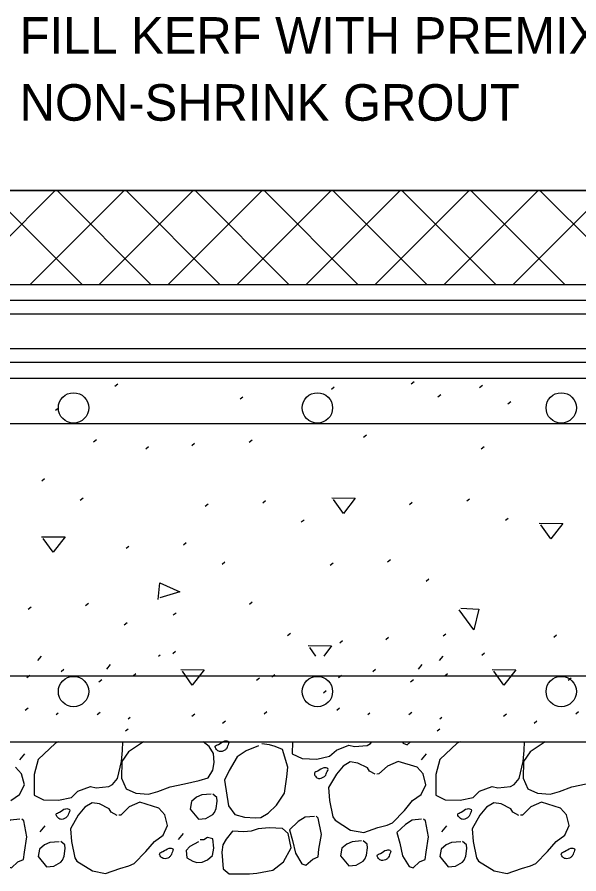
# Model space of a CAD drawing. Extents: x 3239 to 4230, y -4276 to -2494.
# Drawn here: x 3413 to 3459.1, y -4182.4 to -4112.1 of the extents above; entities that cross this region are included whole.
import ezdxf

# ---------------------------------------------------------------- set-up
doc = ezdxf.new("R2010")
doc.units = 0
doc.layers.add('2', color=7, linetype='Continuous')

msp = doc.modelspace()

# ---------------------------------------------------------------- linework, layer by layer
at = {"layer": '2'}
for p, q in [((3367.086, -4126.29), (3545.886, -4126.29)), ((3408.444, -4133.99), (3416.144, -4126.29)), ((3410.64, -4126.29), (3418.34, -4133.99)), ((3414.1, -4133.99), (3421.8, -4126.29)), ((3416.297, -4126.29), (3423.997, -4133.99)), ((3419.757, -4133.99), (3427.457, -4126.29)), ((3421.953, -4126.29), (3429.653, -4133.99)), ((3425.414, -4133.99), (3433.114, -4126.29)), ((3427.61, -4126.29), (3435.31, -4133.99)), ((3431.071, -4133.99), (3438.771, -4126.29)), ((3433.267, -4126.29), (3440.967, -4133.99)), ((3436.728, -4133.99), (3444.428, -4126.29)), ((3438.924, -4126.29), (3446.624, -4133.99)), ((3442.385, -4133.99), (3450.085, -4126.29)), ((3444.581, -4126.29), (3452.281, -4133.99)), ((3448.042, -4133.99), (3455.742, -4126.29)), ((3450.238, -4126.29), (3457.938, -4133.99)), ((3453.698, -4133.99), (3461.398, -4126.29)), ((3455.895, -4126.29), (3463.595, -4133.99)), ((3363.086, -4133.99), (3601.998, -4133.99)), ((3373.167, -4135.293), (3504.55, -4135.293)), ((3365.857, -4136.415), (3504.55, -4136.415)), ((3365.857, -4139.265), (3504.55, -4139.265)), ((3365.857, -4139.265), (3504.55, -4139.265)), ((3373.167, -4140.387), (3504.55, -4140.387)), ((3351.09, -4141.69), (3512.455, -4141.69)), ((3421.032, -4142.344), (3421.265, -4142.158)), ((3445.343, -4142.147), (3445.576, -4141.96)), ((3450.944, -4142.454), (3451.177, -4142.267)), ((3438.796, -4142.589), (3439.029, -4142.403)), ((3447.533, -4143.227), (3447.766, -4143.041)), ((3431.306, -4143.392), (3431.539, -4143.206)), ((3453.27, -4143.791), (3453.503, -4143.605)), ((3416.163, -4144.324), (3416.395, -4144.138)), ((3311.806, -4145.411), (3542.451, -4145.411)), ((3441.429, -4146.527), (3441.662, -4146.34)), ((3419.284, -4146.902), (3419.517, -4146.715)), ((3427.346, -4147.213), (3427.579, -4147.027)), ((3432.049, -4146.931), (3432.282, -4146.745)), ((3423.571, -4147.493), (3423.804, -4147.307)), ((3451.084, -4147.486), (3451.317, -4147.3)), ((3415.032, -4150.106), (3415.265, -4149.92)), ((3418.201, -4151.69), (3418.434, -4151.504)), ((3428.454, -4152.188), (3428.687, -4152.002)), ((3433.157, -4151.906), (3433.39, -4151.719)), ((3445.196, -4152.049), (3445.429, -4151.863)), ((3449.899, -4151.767), (3450.132, -4151.581)), ((3436.326, -4153.49), (3436.559, -4153.304)), ((3453.068, -4153.352), (3453.301, -4153.165)), ((3421.951, -4155.649), (3422.184, -4155.463)), ((3426.654, -4155.367), (3426.887, -4155.18)), ((3429.823, -4156.951), (3430.056, -4156.765)), ((3438.693, -4157.033), (3438.926, -4156.847)), ((3443.396, -4156.751), (3443.629, -4156.565)), ((3446.565, -4158.336), (3446.798, -4158.149)), ((3413.926, -4160.633), (3414.159, -4160.447)), ((3418.629, -4160.351), (3418.862, -4160.164)), ((3432.072, -4160.234), (3432.305, -4160.048)), ((3425.829, -4161.12), (3426.062, -4160.933)), ((3421.798, -4161.935), (3422.031, -4161.749)), ((3435.194, -4162.812), (3435.427, -4162.625)), ((3447.959, -4162.841), (3448.192, -4162.655)), ((3457.025, -4162.933), (3457.258, -4162.746)), ((3439.481, -4163.403), (3439.714, -4163.216)), ((3443.255, -4163.123), (3443.488, -4162.937)), ((3425.782, -4164.288), (3426.015, -4164.102)), ((3424.621, -4164.49), (3424.757, -4164.381)), ((3451.128, -4164.425), (3451.361, -4164.239)), ((3416.622, -4165.75), (3416.855, -4165.563)), ((3442.179, -4165.75), (3442.412, -4165.563)), ((3310.367, -4166.121), (3542.451, -4166.121)), ((3413.821, -4166.243), (3414.054, -4166.056)), ((3422.529, -4166.101), (3422.762, -4165.914)), ((3433.921, -4166.196), (3434.154, -4166.01)), ((3439.378, -4166.243), (3439.611, -4166.056)), ((3448.085, -4166.101), (3448.318, -4165.914)), ((3419.728, -4166.594), (3419.961, -4166.407)), ((3432.663, -4166.476), (3432.896, -4166.29)), ((3445.285, -4166.594), (3445.518, -4166.407)), ((3458.22, -4166.476), (3458.453, -4166.29)), ((3438.143, -4167.505), (3438.376, -4167.318)), ((3413.681, -4168.934), (3413.914, -4168.747)), ((3433.273, -4169.226), (3433.506, -4169.04)), ((3439.238, -4168.934), (3439.471, -4168.747)), ((3458.83, -4169.226), (3459.063, -4169.04)), ((3416.219, -4169.28), (3416.391, -4169.142)), ((3419.588, -4169.285), (3419.821, -4169.098)), ((3422.125, -4169.632), (3422.298, -4169.493)), ((3427.358, -4169.415), (3427.591, -4169.229)), ((3441.776, -4169.28), (3441.948, -4169.142)), ((3445.145, -4169.285), (3445.378, -4169.098)), ((3447.682, -4169.632), (3447.855, -4169.493)), ((3452.915, -4169.415), (3453.148, -4169.229)), ((3421.915, -4170.622), (3422.125, -4170.453)), ((3429.862, -4170), (3430.095, -4169.813)), ((3447.471, -4170.622), (3447.682, -4170.453)), ((3455.419, -4170), (3455.652, -4169.813)), ((3310.367, -4171.521), (3545.886, -4171.521))]:
    msp.add_line(p, q, dxfattribs=at)
msp.add_lwpolyline([(3373.586, -4133.99), (3545.886, -4133.99), (3545.886, -4126.29), (3373.586, -4126.29)], close=True, dxfattribs=at)
for points in [[(3438.818, -4151.513), (3440.751, -4151.536), (3439.773, -4152.794), (3438.957, -4151.653)], [(3455.836, -4153.59), (3457.77, -4153.613), (3456.791, -4154.871), (3455.976, -4153.729)], [(3415.019, -4154.697), (3416.953, -4154.721), (3415.975, -4155.979), (3415.159, -4154.837)], [(3424.594, -4159.838), (3424.734, -4158.487), (3426.364, -4159.233), (3424.71, -4159.722)], [(3449.411, -4160.562), (3450.879, -4160.632), (3450.483, -4162.333), (3449.271, -4160.702)], [(3436.878, -4163.636), (3438.812, -4163.659), (3438.165, -4164.49)], [(3437.528, -4164.49), (3437.018, -4163.776)], [(3414.981, -4164.49), (3414.677, -4164.853)], [(3447.924, -4164.49), (3447.62, -4164.853)], [(3420.658, -4165.192), (3420.354, -4165.555)], [(3446.215, -4165.192), (3445.911, -4165.555)], [(3426.432, -4165.594), (3428.366, -4165.618), (3427.388, -4166.876), (3426.572, -4165.734)], [(3451.989, -4165.594), (3453.923, -4165.618), (3452.945, -4166.876), (3452.129, -4165.734)], [(3416.417, -4171.521), (3416.162, -4171.649), (3414.754, -4172.992), (3414.426, -4174.218), (3414.419, -4175.898), (3415.194, -4176.287), (3416.418, -4176.31), (3417.466, -4176.088), (3418.009, -4175.584), (3419.042, -4175.188), (3419.509, -4175.299), (3420.547, -4175.208), (3420.837, -4175.031), (3421.251, -4174.537), (3421.589, -4173.156), (3421.661, -4172.236), (3421.699, -4171.521)], [(3423.391, -4171.521), (3422.149, -4172.345), (3421.611, -4173.154), (3421.576, -4174.509), (3421.958, -4175.39), (3422.753, -4175.756), (3423.804, -4175.817), (3424.548, -4175.599), (3425.562, -4175.228), (3426.759, -4174.97), (3427.936, -4174.715), (3428.679, -4174.496), (3429.08, -4173.852), (3429.18, -4173.233), (3429.115, -4172.498), (3428.759, -4171.918), (3428.284, -4171.521)], [(3432.808, -4171.869), (3431.796, -4172.263), (3431.077, -4172.762), (3430.413, -4173.888), (3430.026, -4174.684), (3430.36, -4176.769), (3430.88, -4177.486), (3431.661, -4177.701), (3432.562, -4177.774), (3433.016, -4177.734), (3433.595, -4177.38), (3434.301, -4176.729), (3434.956, -4175.756), (3435.142, -4174.39), (3435.227, -4173.62), (3434.793, -4172.153), (3434.184, -4171.903), (3433.715, -4171.79), (3433.098, -4171.692)], [(3435.593, -4171.521), (3435.588, -4172.521), (3436.384, -4172.908), (3437.588, -4172.955), (3438.635, -4172.711), (3439.199, -4172.205), (3440.211, -4171.811), (3440.679, -4171.922), (3441.737, -4171.829), (3442.006, -4171.654), (3442.123, -4171.521)], [(3444.607, -4171.521), (3444.685, -4171.647), (3445.001, -4171.771), (3445.27, -4171.521)], [(3449.361, -4171.521), (3449.105, -4171.649), (3447.698, -4172.992), (3447.37, -4174.218), (3447.363, -4175.898), (3448.138, -4176.287), (3449.361, -4176.31), (3450.41, -4176.088), (3450.953, -4175.584), (3451.986, -4175.188), (3452.453, -4175.299), (3453.491, -4175.208), (3453.781, -4175.031), (3454.195, -4174.537), (3454.533, -4173.156), (3454.604, -4172.236), (3454.643, -4171.521)], [(3456.335, -4171.521), (3455.093, -4172.345), (3454.555, -4173.154), (3454.52, -4174.509), (3454.902, -4175.39), (3455.697, -4175.756), (3456.748, -4175.817), (3457.492, -4175.599), (3458.505, -4175.228), (3459.702, -4174.97), (3460.88, -4174.715), (3461.623, -4174.496), (3462.024, -4173.852), (3462.123, -4173.233), (3462.059, -4172.498), (3461.703, -4171.918), (3461.227, -4171.521)], [(3413.635, -4172.507), (3413.219, -4173.003)], [(3446.578, -4172.507), (3446.163, -4173.003)], [(3442.381, -4174.192), (3441.923, -4173.949), (3441.746, -4173.659), (3440.949, -4173.271), (3440.33, -4173.174), (3439.752, -4173.528), (3439.221, -4174.185), (3438.555, -4175.289), (3438.647, -4176.349), (3438.915, -4177.677), (3439.094, -4177.967), (3440.363, -4178.77), (3441.449, -4178.981), (3442.611, -4178.574), (3443.355, -4178.357), (3443.797, -4178.164), (3444.777, -4177.164), (3445.446, -4176.343), (3446.165, -4175.843), (3446.552, -4175.047), (3446.322, -4174.153), (3445.816, -4173.608), (3444.271, -4173.132), (3443.39, -4173.515), (3442.683, -4174.166), (3442.532, -4174.179)], [(3412.502, -4176.343), (3413.221, -4175.843), (3413.609, -4175.047), (3413.379, -4174.153), (3412.872, -4173.608)], [(3428.926, -4175.826), (3428.169, -4175.893), (3427.729, -4176.085), (3427.323, -4176.424), (3427.224, -4177.043), (3427.886, -4177.88), (3428.189, -4177.853), (3428.492, -4177.827), (3429.072, -4177.492), (3429.211, -4177.327), (3429.335, -4177.012), (3429.433, -4176.393), (3429.406, -4176.09), (3429.242, -4175.952), (3429.078, -4175.813)], [(3421.213, -4177.569), (3420.731, -4177.306), (3420.554, -4177.016), (3419.779, -4176.627), (3419.16, -4176.529), (3418.58, -4176.885), (3418.029, -4177.542), (3417.386, -4178.666), (3417.477, -4179.705), (3417.747, -4181.054), (3417.924, -4181.322), (3419.192, -4182.126), (3420.279, -4182.336), (3421.441, -4181.929), (3422.184, -4181.712), (3422.625, -4181.52), (3423.585, -4180.543), (3424.276, -4179.721), (3424.995, -4179.201), (3425.361, -4178.404), (3425.131, -4177.532), (3424.645, -4176.963), (3423.079, -4176.492), (3422.218, -4176.87), (3421.514, -4177.543), (3421.364, -4177.556)], [(3454.157, -4177.569), (3453.675, -4177.306), (3453.498, -4177.016), (3452.723, -4176.627), (3452.104, -4176.529), (3451.524, -4176.885), (3450.973, -4177.542), (3450.33, -4178.666), (3450.421, -4179.705), (3450.691, -4181.054), (3450.868, -4181.322), (3452.136, -4182.126), (3453.222, -4182.336), (3454.385, -4181.929), (3455.128, -4181.712), (3455.568, -4181.52), (3456.529, -4180.543), (3457.22, -4179.721), (3457.939, -4179.201), (3458.304, -4178.404), (3458.074, -4177.532), (3457.589, -4176.963), (3456.023, -4176.492), (3455.162, -4176.87), (3454.458, -4177.543), (3454.307, -4177.556)], [(3413.242, -4177.888), (3412.484, -4177.955), (3411.928, -4178.309), (3411.222, -4178.959), (3411.452, -4179.854), (3411.695, -4180.878), (3412.229, -4181.748), (3412.545, -4181.872), (3413.088, -4181.367), (3413.53, -4181.175), (3413.63, -4180.579), (3413.827, -4179.34), (3413.557, -4178.014), (3413.393, -4177.875)], [(3437.41, -4177.655), (3436.653, -4177.722), (3436.074, -4178.078), (3435.37, -4178.75), (3435.6, -4179.622), (3435.843, -4180.669), (3436.377, -4181.538), (3436.693, -4181.663), (3437.259, -4181.156), (3437.7, -4180.964), (3437.776, -4180.348), (3437.975, -4179.131), (3437.705, -4177.783), (3437.539, -4177.644)], [(3446.186, -4177.888), (3445.428, -4177.955), (3444.871, -4178.309), (3444.166, -4178.959), (3444.396, -4179.854), (3444.639, -4180.878), (3445.172, -4181.748), (3445.489, -4181.872), (3446.032, -4181.367), (3446.474, -4181.175), (3446.573, -4180.579), (3446.77, -4179.34), (3446.501, -4178.014), (3446.337, -4177.875)], [(3415.301, -4178.429), (3414.885, -4178.924)], [(3431.616, -4178.925), (3430.694, -4178.854), (3430.164, -4179.511), (3429.901, -4179.991), (3429.8, -4180.587), (3429.919, -4181.95), (3430.414, -4182.365), (3432.068, -4182.351), (3432.674, -4182.298), (3434.004, -4182.051), (3434.858, -4181.366), (3435.501, -4180.242), (3435.246, -4179.066), (3434.774, -4178.648), (3433.701, -4178.591), (3432.792, -4178.67), (3432.222, -4178.872), (3431.616, -4178.925)], [(3448.245, -4178.429), (3447.829, -4178.924)], [(3426.637, -4179.057), (3426.223, -4179.55)], [(3427.901, -4179.75), (3427.171, -4180.12), (3426.896, -4180.449), (3426.949, -4181.053), (3427.429, -4181.317), (3427.746, -4181.443), (3428.199, -4181.403), (3428.64, -4181.211), (3429.045, -4180.87), (3429.145, -4180.252), (3429.079, -4179.496), (3428.633, -4179.381), (3428.343, -4179.56), (3428.04, -4179.586)], [(3416.457, -4179.727), (3415.7, -4179.794), (3415.26, -4179.986), (3414.854, -4180.325), (3414.754, -4180.944), (3415.417, -4181.781), (3415.72, -4181.754), (3416.023, -4181.728), (3416.602, -4181.393), (3416.742, -4181.228), (3416.866, -4180.913), (3416.963, -4180.294), (3416.937, -4179.991), (3416.773, -4179.853), (3416.609, -4179.714)], [(3441.256, -4179.658), (3440.499, -4179.724), (3440.059, -4179.916), (3439.653, -4180.255), (3439.553, -4180.875), (3440.216, -4181.711), (3440.519, -4181.685), (3440.822, -4181.658), (3441.401, -4181.324), (3441.541, -4181.158), (3441.665, -4180.843), (3441.762, -4180.224), (3441.736, -4179.921), (3441.572, -4179.784), (3441.408, -4179.644)], [(3449.4, -4179.727), (3448.644, -4179.794), (3448.203, -4179.986), (3447.798, -4180.325), (3447.698, -4180.944), (3448.36, -4181.781), (3448.664, -4181.754), (3448.967, -4181.728), (3449.546, -4181.393), (3449.685, -4181.228), (3449.81, -4180.913), (3449.907, -4180.294), (3449.881, -4179.991), (3449.717, -4179.853), (3449.553, -4179.714)]]:
    msp.add_lwpolyline(points, dxfattribs=at)
for centre in [(3417.646, -4144.128), (3437.646, -4144.128), (3457.646, -4144.128), (3417.646, -4167.404), (3437.646, -4167.404), (3457.646, -4167.404)]:
    msp.add_circle(centre, 1.247, dxfattribs=at)
for points in [[(3430.278, -4171.852), (3430.209, -4172.053), (3430.049, -4172.221), (3429.622, -4172.323), (3429.367, -4172.149), (3429.258, -4171.896), (3429.528, -4171.743), (3430.047, -4171.457), (3430.358, -4171.518), (3430.259, -4171.876)], [(3438.404, -4174.061), (3438.333, -4174.263), (3438.172, -4174.407), (3437.748, -4174.532), (3437.492, -4174.358), (3437.405, -4174.104), (3437.673, -4173.928), (3438.172, -4173.666), (3438.505, -4173.725), (3438.404, -4174.061)], [(3417.234, -4177.417), (3417.163, -4177.618), (3417.002, -4177.764), (3416.577, -4177.888), (3416.322, -4177.713), (3416.213, -4177.463), (3416.483, -4177.307), (3417.002, -4177.023), (3417.313, -4177.083), (3417.235, -4177.438)], [(3450.177, -4177.417), (3450.106, -4177.618), (3449.946, -4177.764), (3449.521, -4177.888), (3449.266, -4177.713), (3449.157, -4177.463), (3449.427, -4177.307), (3449.946, -4177.023), (3450.257, -4177.083), (3450.179, -4177.438)], [(3425.708, -4180.641), (3425.639, -4180.843), (3425.478, -4181.01), (3425.052, -4181.113), (3424.8, -4180.959), (3424.711, -4180.707), (3424.979, -4180.53), (3425.48, -4180.269), (3425.787, -4180.307), (3425.71, -4180.663)], [(3458.652, -4180.641), (3458.583, -4180.843), (3458.422, -4181.01), (3457.996, -4181.113), (3457.744, -4180.959), (3457.655, -4180.707), (3457.923, -4180.53), (3458.424, -4180.269), (3458.731, -4180.307), (3458.654, -4180.663)], [(3443.561, -4180.803), (3443.491, -4181.004), (3443.33, -4181.15), (3442.905, -4181.274), (3442.65, -4181.099), (3442.541, -4180.849), (3442.811, -4180.693), (3443.33, -4180.407), (3443.641, -4180.469), (3443.542, -4180.826)]]:
    msp.add_spline(points, degree=3, dxfattribs=at)

# ---------------------------------------------------------------- texts
for s, p in [('FILL KERF WITH PREMIXED ', (3413.225, -4115.061)), ('NON-SHRINK GROUT', (3413.225, -4120.561))]:
    msp.add_text(s, height=3, dxfattribs=at).set_placement(p)

doc.saveas('drawing.dxf')
